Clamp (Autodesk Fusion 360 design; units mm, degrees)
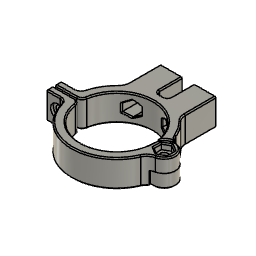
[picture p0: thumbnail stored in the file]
sketch "Sketch1" plane through (0, 0, 0) normal (0, 0, 1) x axis (1, 0, 0)
  line L1 (0, 3.3486) -> (2.9, 1.6743)
  line L2 (-2.9, 1.6743) -> (0, 3.3486)
  line L3 (-2.9, -1.6743) -> (-2.9, 1.6743)
  line L4 (0, -3.3486) -> (-2.9, -1.6743)
  line L5 (2.9, -1.6743) -> (0, -3.3486)
  line L6 (2.9, 1.6743) -> (2.9, -1.6743)
  line L7 (10, 0) -> (0, 0)
  line L8 (-9.853, 0) -> (0, 0)
  line L9 (-9.853, 0) -> (-40, 0)
  line L10 (-41.196, 0.4) -> (-37.195, 0.4)
  line L11 (-37.195, -0.4) -> (-41.196, -0.4)
  line L12 (-49.196, 0.4) -> (-37.195, 0.4)
  line L13 (-49.196, 3.4) -> (-49.196, 0.4)
  line L14 (-37.195, 3.4) -> (-49.196, 3.4)
  line L15 (-37.195, 0.4) -> (-37.195, 3.4)
  line L16 (-49.196, -0.4) -> (-37.195, -0.4)
  line L17 (-49.196, -3.4) -> (-49.196, -0.4)
  line L18 (-37.195, -3.4) -> (-49.196, -3.4)
  line L19 (-37.195, -0.4) -> (-37.195, -3.4)
  line L20 (-21.1, 48.6647) -> (-21.1, 0)
  line L21 (-13.6, 19) -> (-13.6, 45)
  line L22 (-28.6, 19) -> (-28.6, 45)
  line L23 (-33.6, 32.1) -> (-23.6, 32.1)
  line L24 (-33.6, 15.7404) -> (-33.6, 32.1)
  line L25 (-23.6, 15.7404) -> (-33.6, 15.7404)
  line L26 (-23.6, 32.1) -> (-23.6, 15.7404)
  line L27 (-8.6, 32.1) -> (-18.6, 32.1)
  line L28 (-8.6, 15.7404) -> (-8.6, 32.1)
  line L29 (-18.6, 15.7404) -> (-8.6, 15.7404)
  line L30 (-18.6, 32.1) -> (-18.6, 15.7404)
  line L31 (-11, 20.1) -> (-31, 20.1)
  circle C1 centre (0, 0) radius 3
  circle C2 centre (0, 0) radius 5
  circle C3 centre (0, 0) radius 1.75
  circle C4 centre (0, 0) radius 5.25
  circle C5 centre (-21.1, 0) radius 16.1
  circle C6 centre (-21.1, 0) radius 20.1
  point P1 (0, 0)
  point P2 (0, 0)
  point P11 (0, 0)
  point P12 (0, 0)
  point P14 (0, 0)
  point P20 (-37.195, 0.4)
  point P21 (-41.196, 0.4)
  point P22 (-41.196, -0.4)
  point P23 (-37.195, -0.4)
  point P16 (-21.1, 0)
  point P30 (-21.1, 0)
  point P38 (-33.6, 15.7404)
  point P42 (-8.6, 15.7404)
  coincident P1 P2
  concentric C1 C3
  coincident P2 P11
  coincident P1 P12
  perpendicular L6 L7
  coincident P2 P14
  parallel L7 L8
  horizontal L9
  coincident C5 P20
  coincident C6 P21
  parallel L9 L10
  coincident C6 P22
  coincident C5 P23
  parallel L9 L11
  horizontal L12
  vertical L13
  horizontal L14
  vertical L15
  horizontal L16
  vertical L17
  horizontal L18
  vertical L19
  tangent C2 C5
  coincident P16 P30
  vertical L20
  coincident P16 L9
  parallel L20 L21
  vertical L22
  horizontal L23
  vertical L24
  horizontal L25
  vertical L26
  coincident C6 P38
  horizontal L27
  vertical L28
  horizontal L29
  vertical L30
  coincident C6 P42
  perpendicular L21 L31
  tangent C6 L31
  dimension "d1" diameter C1 = 6
  dimension "d2" = 2
  dimension "d3" diameter C3 = 3.5
  dimension "d4" distance P11 L6 = 2.9
  dimension "d23" = 2.25
  dimension "d35" diameter C5 = 32.2
  dimension "d36" = 4
  dimension "d37" distance L10 L11 = 0.8
  dimension "d38" distance L9 L10 = 0.4 (= "d37 / 2")
  dimension "d39" distance P21 L13 = 8
  dimension "d40" distance P22 L17 = 8
  dimension "d41" distance L12 L14 = 3
  dimension "d42" distance L16 L18 = 3
  dimension "d112" distance L20 L22 = 7.5
  dimension "d113" distance L20 L21 = 7.5
  dimension "d114" distance L22 L24 = 5
  dimension "d115" distance L22 L26 = 5
  dimension "d116" distance L21 L30 = 5
  dimension "d117" distance L21 L28 = 5
  dimension "d118" distance L23 L31 = 12
  dimension "d119" distance L27 L31 = 12 (= "d118")
extrude "Extrude8" new body sketch "Sketch1" profile of C1 C2 L1 L2 L3 L4 L5 L6 C4 C5 C6 L10 L11 L12 L13 L14 L15 L16 L17 L18 L19 L23 L24 L25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 along normal blind 3
extrude "Extrude9" add sketch "Sketch1" profile of C1 C2 C3 L1 L2 L3 L4 L5 L6 C4 C5 C6 L10 L11 L12 L13 L14 L15 L16 L17 L18 L19 L23 L24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 blind 3 from offset 3
extrude "Extrude10" add sketch "Sketch1" profile of C1 C2 C3 L1 L2 L3 L4 L5 L6 C4 C5 C6 L11 L16 L17 L18 L19 blind 3.4 from offset 6
extrude "Extrude11" add sketch "Sketch1" profile of C1 C2 L1 L2 L3 L4 L5 L6 C4 C5 C6 L11 L16 L17 L18 L19 blind 2.6 from offset 9.4
extrude "Extrude12" add sketch "Sketch1" profile of C4 C5 C6 L10 L12 L13 L14 L15 L23 L24 L25 L26 L27 L28 L29 L30 blind 6 from offset 6
sketch "Sketch2" plane through (0, -3.4, 0) normal (0, -1, 0) x axis (1, 0, 0)
  line L1 (-40.9104, 0) -> (-49.196, 0)
  line L2 (-40.9104, 12) -> (-40.9104, 0)
  line L3 (-49.196, 12) -> (-40.9104, 12)
  line L4 (-49.196, 0) -> (-49.196, 12)
  line L5 (-47.196, 2.0461) -> (-47.196, 10.8025)
  line L6 (-44.196, 2.7091) -> (-47.046, 4.3546)
  line L7 (-41.346, 4.3546) -> (-44.196, 2.7091)
  line L8 (-41.346, 7.6454) -> (-41.346, 4.3546)
  line L9 (-44.196, 9.2909) -> (-41.346, 7.6454)
  line L10 (-47.046, 7.6454) -> (-44.196, 9.2909)
  line L11 (-47.046, 4.3546) -> (-47.046, 7.6454)
  circle C1 centre (-44.196, 6) radius 3
  circle C2 centre (-44.196, 6) radius 1.75
  point P8 (-44.196, 6)
  point P16 (-44.196, 6)
  vertical L5
  tangent L5 C1
  concentric C1 C2
  coincident P8 P16
  dimension "d57" distance L4 L5 = 2
  dimension "d58" diameter C1 = 6
  dimension "d59" distance L3 P8 = 6
  dimension "d60" diameter C2 = 3.5
  dimension "d61" distance P16 L11 = 2.85
extrude "Extrude13" cut sketch "Sketch2" profile of C2 against normal blind 10
extrude "Extrude14" cut sketch "Sketch2" profile of C1 C2 L6 L7 L8 L9 L10 L11 against normal blind 1.2
extrude "Extrude15" cut sketch "Sketch2" profile of C1 C2 L6 L7 L8 L9 L10 L11 blind -3.4 from offset -4.4
work_plane "WorkPlane1" AlongDistance -12
sketch "Sketch3" plane through (-13.5, 20.1, 6) normal (0, 1, 0) x axis (1, 0, 0)
  line L1 (-4.5, 5.5) -> (4.5, -5.5)
  line L2 (4.5, 5.5) -> (-4.5, -5.5)
  line L3 (-19.5, 5.5) -> (-10.5, -5.5)
  line L4 (-19.5, -5.5) -> (-10.5, 5.5)
  line L5 (0, -3.2909) -> (-2.85, -1.6454)
  line L6 (2.85, -1.6454) -> (0, -3.2909)
  line L7 (2.85, 1.6454) -> (2.85, -1.6454)
  line L8 (0, 3.2909) -> (2.85, 1.6454)
  line L9 (-2.85, 1.6454) -> (0, 3.2909)
  line L10 (-2.85, -1.6454) -> (-2.85, 1.6454)
  line L11 (-15, -3.2909) -> (-17.85, -1.6454)
  line L12 (-12.15, -1.6454) -> (-15, -3.2909)
  line L13 (-12.15, 1.6454) -> (-12.15, -1.6454)
  line L14 (-15, 3.2909) -> (-12.15, 1.6454)
  line L15 (-17.85, 1.6454) -> (-15, 3.2909)
  line L16 (-17.85, -1.6454) -> (-17.85, 1.6454)
  circle C1 centre (0, 0) radius 1.75
  circle C2 centre (-15, 0) radius 1.75
  point P10 (-15, 0)
  point P1 (0, 0)
  point P17 (0, 0)
  point P24 (-15, 0)
  point P25 (0, 0)
  point P26 (-15, 0)
  midpoint L4 P10
  coincident P1 P17
  coincident P10 P24
  coincident P17 P25
  coincident P10 P26
  dimension "d126" distance P17 L10 = 2.85
  dimension "d127" distance P24 L16 = 2.85
  dimension "d128" diameter C1 = 3.5
  dimension "d129" diameter C2 = 3.5
extrude "Extrude16" cut sketch "Sketch3" profile of L5 L6 L7 L8 L9 L10 L11 L12 L13 L14 L15 L16 C1 C2 against normal blind 8
extrude "Extrude17" cut sketch "Sketch3" profile of C1 C2 along normal blind 12
fillet "Fillet2" radius 5 2.5 5 1.5 2.5
chamfer "Chamfer3" distance 0.5 distance 1 distance 0.5 distance 0.5 distance 0.4
component_from_bodies "Body->Comp2"
component_from_bodies "Body->Comp3"
joint "Assemble1" alignAngle 0 alignOffsetX 0 alignOffsetY 0 alignOffsetZ 0 AngleMinimum -180 AngleMaximum 1 AngleRest 0
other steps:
base_feature "Base Feature1"
base_feature "Base Feature1"
create_component "CreateComponent2"
remove_body "RemoveBody3"
create_component "CreateComponent3"
remove_body "RemoveBody5"
joint_origin "JointOrigin4"
joint_origin "JointOrigin4"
